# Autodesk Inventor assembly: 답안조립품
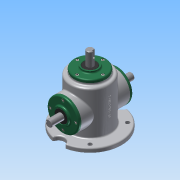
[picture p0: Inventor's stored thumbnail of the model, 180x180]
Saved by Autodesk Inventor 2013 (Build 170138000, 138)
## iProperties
Created: 2018-04
Part Number: 답안조립품
Document SubType Name: Assembly
Designer: Administrator
Author: Administrator
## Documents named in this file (16)
- C:\Users\Administrator\Desktop\480408V1009\답안조립품.iam
- C:\Users\Administrator\Desktop\480408V1009\메인 베벨기어.ipt
- C:\Users\Administrator\Desktop\480408V1009\메인 축.ipt
- 메인 축.ipt
- C:\Users\Administrator\Desktop\480408V1009\베어링 6203.ipt
- C:\Users\Administrator\Desktop\480408V1009\본체.ipt
- C:\Users\Administrator\Desktop\480408V1009\볼트 M4.ipt
- 볼트 M4.ipt
- C:\Users\Administrator\Desktop\480408V1009\서브 베벨기어.ipt
- C:\Users\Administrator\Desktop\480408V1009\서브 축.ipt
- 서브 축.ipt
- C:\Users\Administrator\Desktop\480408V1009\오일 실.ipt
- 오일 실.ipt
- C:\Users\Administrator\Desktop\480408V1009\커버.ipt
- C:\Users\Administrator\Desktop\480408V1009\키 4x4.ipt
- C:\Users\Administrator\Desktop\480408V1009\키 5x5.ipt
